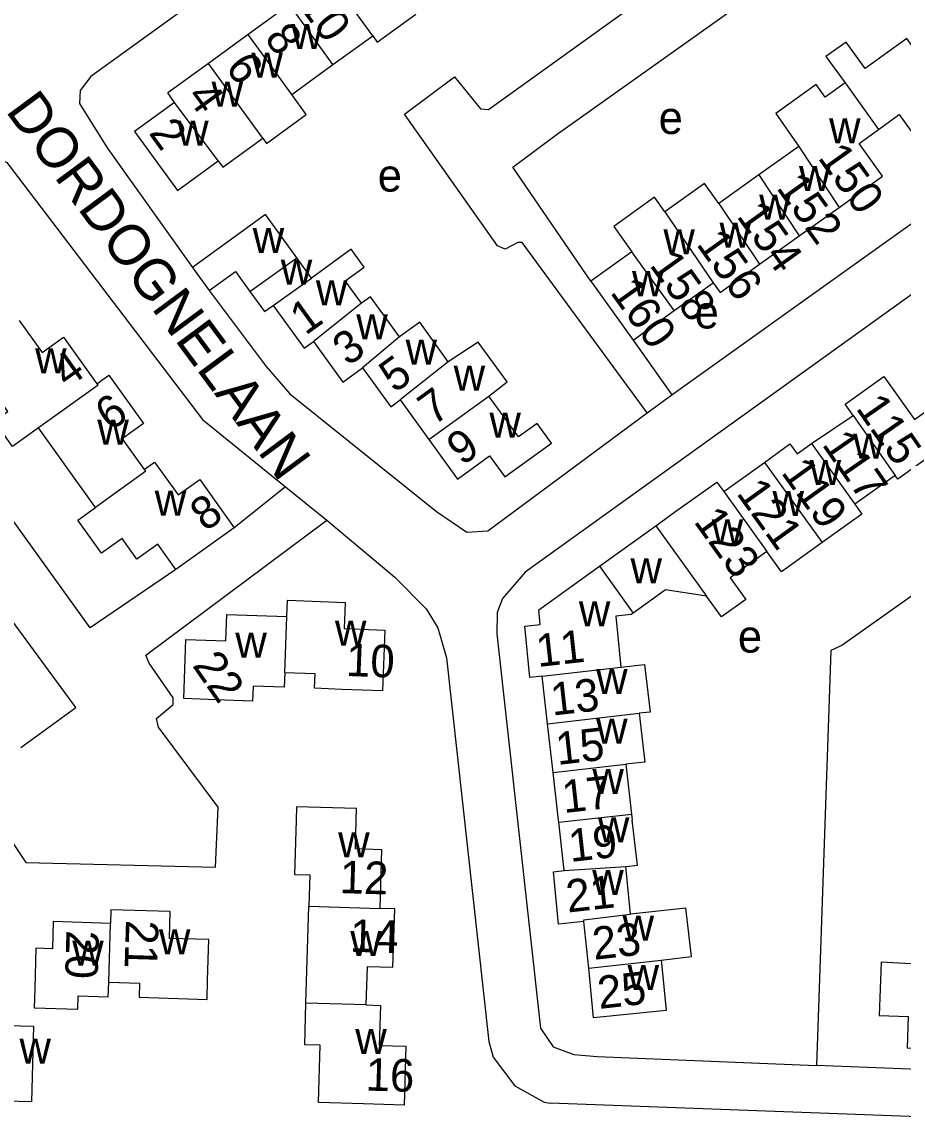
# Model space of a CAD drawing. Extents: x 157768 to 159790, y 387230 to 389604.
# Drawn here: x 159313.5 to 159421.7, y 387713.3 to 387848 of the extents above; entities that cross this region are included whole.
import ezdxf

# ---------------------------------------------------------------- set-up
doc = ezdxf.new("R2010")
doc.units = 0
for name, color, linetype in [('BLT_Basislijn', 7, 'Continuous'), ('BLT_Bebouwing', 7, 'Continuous'), ('BLT_Centroide', 7, 'Continuous'), ('BLT_Huisnummer', 7, 'Continuous'), ('BLT_Huisnummer_ tussenligend', 7, 'Continuous'), ('BLT_Onderverdeling_panden', 7, 'Continuous'), ('BLT_Straatnaam', 7, 'Continuous')]:
    doc.layers.add(name, color=color, linetype=linetype)

msp = doc.modelspace()

# ---------------------------------------------------------------- linework, layer by layer
at = {"layer": 'BLT_Basislijn'}
for p, q in [((159388.55, 387808.92), (159393.32, 387802.2)), ((159390.28, 387799.97), (159393.32, 387802.2)), ((159345.89, 387790.89), (159339.59, 387785.87)), ((159345.89, 387790.89), (159350.94, 387786.79))]:
    msp.add_line(p, q, dxfattribs=at)
for points in [[(159369.02, 387875.27), (159321.99, 387841.27), (159320.67, 387839.54), (159320.57, 387837.93), (159324, 387832.5), (159334.45, 387817.83)], [(159390.28, 387799.97), (159374.93, 387820.87), (159374.4, 387820.9), (159372.85, 387820.06), (159371.89, 387820.49), (159360.49, 387836.65), (159366.62, 387841.23), (159369.82, 387837.31), (159370.78, 387837.23), (159412.51, 387867.2)], [(159383.37, 387816.16), (159373.78, 387830.14), (159379.12, 387834.12), (159416.97, 387861.01)], [(159393.32, 387802.2), (159394.32, 387802.93), (159437.92, 387834.07), (159438.12, 387834.28)], [(159219.5, 387769.45), (159262.12, 387800.73), (159305.97, 387831.61), (159309.16, 387831.8), (159311.67, 387830.69), (159335.68, 387799.17), (159345.89, 387790.89)], [(159445.3, 387826.26), (159440.05, 387825.99), (159434.86, 387823.21), (159375.3, 387780.41), (159372.53, 387777.2), (159371.86, 387775.48), (159371.82, 387772.86), (159377.17, 387724.46), (159378.74, 387722.16), (159381.29, 387721.21), (159384.15, 387720.97), (159411.05, 387719.86)], [(159336.49, 387814.98), (159343.52, 387805.65), (159346.42, 387802.32), (159364.42, 387787.88), (159368.15, 387785.35), (159370.7, 387785.49), (159390.28, 387799.97)], [(159332.42, 387780.74), (159321.9, 387773.6), (159309.5, 387790.76), (159307.4, 387793.43), (159306.23, 387794.04), (159272.12, 387769.71), (159266.7, 387765.6), (159264.67, 387762.77), (159241.21, 387746.13), (159238.71, 387746.33), (159236.06, 387744.01), (159232.04, 387749.26)], [(159307.37, 387754.7), (159314, 387744.78), (159337.28, 387744.2), (159337.6, 387751.56), (159330.28, 387761.42), (159330.06, 387762.45), (159332.09, 387764.2), (159332.09, 387765), (159329.13, 387769.25), (159328.74, 387770.25), (159350.94, 387786.79)], [(159350.94, 387786.79), (159359.3, 387779.83), (159363.14, 387775.91), (159364.57, 387773.6), (159365.65, 387769.93), (159370.85, 387722.83), (159371.39, 387720.88), (159374.04, 387717.39), (159377.63, 387715.38), (159378.37, 387715.23)], [(159313.39, 387758.89), (159320.15, 387763.81), (159306.22, 387782.73), (159298.09, 387777.75)], [(159424.28, 387778.6), (159414.19, 387771.43), (159412.82, 387770.79), (159411.05, 387719.86)], [(159452.31, 387759.99), (159452.15, 387759.68), (159439.38, 387720.69), (159436.61, 387719.06), (159434, 387718.98), (159411.05, 387719.86)], [(159535.77, 387748.36), (159535.14, 387748.73), (159527.81, 387753.01), (159522.21, 387754.81), (159457.94, 387756.72), (159444.24, 387717.83), (159443.55, 387716.48), (159440.68, 387713.82), (159439.41, 387713.3), (159428, 387713.39), (159378.37, 387715.23)]]:
    msp.add_lwpolyline(points, dxfattribs=at)
at = {"layer": 'BLT_Bebouwing'}
for p, q in [((159346.35, 387850.09), (159341.3, 387846.43)), ((159341.3, 387846.43), (159336.41, 387842.88)), ((159336.41, 387842.88), (159331.42, 387839.27)), ((159346.64, 387839.07), (159351.69, 387842.73)), ((159332.27, 387838.09), (159331.42, 387839.27)), ((159408.88, 387832.68), (159404, 387829.19)), ((159404, 387829.19), (159399.08, 387825.66)), ((159408.95, 387821.7), (159413.83, 387825.2)), ((159404.07, 387818.21), (159408.95, 387821.7)), ((159388.4, 387819.76), (159383.37, 387816.16)), ((159383.37, 387816.16), (159388.55, 387808.92)), ((159393.59, 387812.53), (159398.37, 387815.95)), ((159388.55, 387808.92), (159393.59, 387812.53)), ((159359.95, 387801.56), (159363.47, 387796.71)), ((159410.43, 387796.2), (159415.58, 387799.65)), ((159407.8, 387796.16), (159408.67, 387794.94)), ((159408.67, 387794.94), (159410.43, 387796.2)), ((159399.67, 387790.31), (159404.66, 387793.9)), ((159339.59, 387785.87), (159332.42, 387780.74)), ((159384.43, 387781.15), (159391.34, 387786.12)), ((159386.42, 387775.04), (159387.05, 387768.76)), ((159378.04, 387761.81), (159377.37, 387767.66)), ((159378.72, 387755.83), (159378.04, 387761.81)), ((159387.65, 387756.85), (159388.36, 387750.74)), ((159379.39, 387750), (159378.72, 387755.83)), ((159388.36, 387750.74), (159388.44, 387750)), ((159379.43, 387749.72), (159379.39, 387750)), ((159380.1, 387743.79), (159379.43, 387749.72)), ((159388.24, 387738.45), (159387.65, 387744.31)), ((159383.1, 387731.8), (159382.52, 387737.55))]:
    msp.add_line(p, q, dxfattribs=at)
for points in [[(159356.58, 387846.27), (159357.15, 387845.47), (159361.89, 387848.91)], [(159351.69, 387842.73), (159356.58, 387846.27)], [(159424.73, 387842.32), (159422.16, 387845.91), (159417.02, 387842.23), (159414.7, 387845.47), (159412.22, 387843.71), (159414.57, 387840.48)], [(159414.57, 387840.48), (159412.13, 387838.73), (159411.02, 387840.27), (159406.05, 387836.71), (159408.88, 387832.68)], [(159332.27, 387838.09), (159327.35, 387834.52), (159332.61, 387827.26), (159337.63, 387830.9)], [(159343.08, 387833.68), (159343.54, 387833.04), (159348.43, 387836.59), (159346.64, 387839.07)], [(159418.67, 387834.76), (159421.22, 387836.58), (159424.94, 387831.39), (159429.97, 387834.99)], [(159413.83, 387825.2), (159419.18, 387829.02), (159416.29, 387833.05), (159418.67, 387834.76)], [(159337.63, 387830.9), (159338.18, 387830.13), (159343.08, 387833.68)], [(159399.08, 387825.66), (159397.31, 387828.12), (159392.44, 387824.64)], [(159392.44, 387824.64), (159391.19, 387826.45), (159386.19, 387822.87), (159388.4, 387819.76)], [(159347.25, 387819.02), (159345.46, 387821.49), (159343.41, 387824.32), (159334.45, 387817.83)], [(159355.2, 387813.44), (159353.22, 387816.17), (159355.55, 387817.86), (159353.95, 387820.06), (159349.06, 387816.52)], [(159334.45, 387817.83), (159336.49, 387814.98)], [(159349.06, 387816.52), (159347.25, 387819.02)], [(159398.37, 387815.95), (159399.23, 387814.74), (159404.07, 387818.21)], [(159336.49, 387814.98), (159339.73, 387817.33), (159341.51, 387814.86)], [(159341.51, 387814.86), (159343.3, 387812.4), (159344.36, 387813.17)], [(159359.89, 387809.3), (159356.31, 387814.24), (159355.2, 387813.44)], [(159344.36, 387813.17), (159348.17, 387807.92), (159349.3, 387808.73)], [(159313.19, 387811.32), (159316, 387807.39), (159318.63, 387809.28), (159322.72, 387803.56)], [(159365.86, 387806.25), (159362.35, 387811.09), (159359.89, 387809.3)], [(159349.3, 387808.73), (159352.91, 387803.74), (159355.34, 387805.5)], [(159370.83, 387802.04), (159373.07, 387803.78), (159369.53, 387808.66), (159365.86, 387806.25)], [(159315.56, 387798.14), (159312.35, 387795.84), (159310.12, 387798.96), (159311.8, 387800.16), (159306.99, 387806.89)], [(159322.72, 387803.56), (159324.19, 387804.61), (159328.44, 387798.68), (159325.82, 387796.81), (159328.53, 387793.02)], [(159355.34, 387805.5), (159358.8, 387800.72), (159359.95, 387801.56)], [(159415.58, 387799.65), (159414.59, 387801.03), (159419.32, 387804.43), (159423.1, 387799.18), (159425.66, 387801.02)], [(159363.47, 387796.71), (159366.98, 387791.86), (159370.93, 387794.71), (159372.8, 387792.12), (159378.52, 387796.27), (159376.76, 387798.69), (159374.46, 387797.03), (159370.83, 387802.04)], [(159322.55, 387788.36), (159315.56, 387798.14)], [(159404.66, 387793.9), (159407.8, 387796.16)], [(159429.84, 387795.21), (159427.36, 387793.43), (159425.97, 387795.36), (159421.06, 387791.83), (159420.71, 387792.31)], [(159328.53, 387793.02), (159329.8, 387793.93), (159332.69, 387789.9), (159335.35, 387791.8), (159339.59, 387785.87)], [(159420.71, 387792.31), (159415.77, 387788.76)], [(159391.34, 387786.12), (159393.81, 387787.9), (159398.81, 387791.49)], [(159398.81, 387791.49), (159399.67, 387790.31)], [(159332.42, 387780.74), (159330.19, 387783.86), (159327.63, 387782.03), (159325.83, 387784.56), (159323.3, 387782.75), (159320.39, 387786.82), (159322.55, 387788.36)], [(159415.77, 387788.76), (159416.63, 387787.56), (159411.76, 387784.06)], [(159404.96, 387782.97), (159400.46, 387779.74), (159402.38, 387777.08)], [(159411.76, 387784.06), (159406.76, 387780.46), (159404.96, 387782.97)], [(159377.16, 387774), (159376.98, 387775.79), (159384.43, 387781.15)], [(159397.56, 387777.49), (159392.54, 387778.27), (159388.56, 387775.41)], [(159402.38, 387777.08), (159399.4, 387774.93), (159397.56, 387777.49)], [(159346.05, 387774.97), (159346.13, 387776.98), (159353.2, 387776.71), (159353.08, 387773.51), (159358.06, 387773.32), (159357.78, 387765.86), (159352.78, 387766.04), (159349.43, 387766.17), (159349.5, 387767.93), (159345.79, 387768.07)], [(159345.79, 387768.07), (159345.72, 387766.29), (159341.9, 387766.43), (159341.83, 387764.59), (159338.38, 387764.72), (159333.39, 387764.9), (159333.66, 387772.17), (159338.56, 387771.98), (159338.68, 387775.24), (159346.05, 387774.97)], [(159388.56, 387775.41), (159388.31, 387775.23), (159386.42, 387775.04)], [(159377.37, 387767.66), (159375.87, 387767.48), (159375.24, 387773.8), (159377.16, 387774)], [(159387.05, 387768.76), (159389.96, 387769.1), (159390.64, 387763.26), (159389.28, 387763.1)], [(159389.28, 387763.1), (159389.97, 387757.12), (159387.65, 387756.85)], [(159354.56, 387750), (159354.6, 387751.42), (159347.24, 387751.64), (159347.19, 387750)], [(159347.19, 387750), (159346.98, 387743.31), (159348.86, 387743.26), (159348.75, 387739.42)], [(159357.49, 387739.16), (159357.71, 387746.35), (159354.45, 387746.45), (159354.56, 387750)], [(159387.65, 387744.31), (159389.08, 387744.46), (159388.44, 387750)], [(159382.52, 387737.55), (159379.4, 387737.23), (159378.76, 387743.64), (159380.1, 387743.79)], [(159324.17, 387730.1), (159327.95, 387729.99), (159327.9, 387728.24), (159336.25, 387727.99), (159336.32, 387730.33), (159336.47, 387735.33), (159331.62, 387735.47), (159331.72, 387738.76), (159324.44, 387738.98), (159324.39, 387737.32)], [(159348.38, 387727.52), (159348.75, 387739.42)], [(159355.8, 387727.3), (159355.94, 387732.02), (159359.06, 387731.93), (159359.28, 387739.1), (159357.49, 387739.16)], [(159392, 387732.82), (159395.7, 387733.25), (159395.02, 387739.17), (159388.24, 387738.45)], [(159324.39, 387737.32), (159317.37, 387737.53), (159317.27, 387734.21), (159315.24, 387734.27), (159315.1, 387729.27), (159315.03, 387726.96), (159320.39, 387726.8), (159320.44, 387728.43), (159324.12, 387728.32), (159324.17, 387730.1)], [(159392, 387732.82), (159392.12, 387731.6), (159392.62, 387726.62), (159383.7, 387725.73), (159383.1, 387731.8)], [(159426.24, 387732.15), (159418.99, 387732.56), (159418.77, 387726.02), (159422.3, 387725.89), (159422.18, 387722.06), (159431.41, 387721.76), (159431.54, 387725.56), (159432.83, 387725.51), (159433.04, 387731.93)], [(159355.8, 387727.3), (159357.52, 387727.24), (159357.37, 387722.34), (159360.66, 387722.24), (159360.44, 387714.99), (159355.44, 387715.15), (159349.93, 387715.31), (159350.14, 387722.36), (159348.23, 387722.42), (159348.38, 387727.52)], [(159311.73, 387724.79), (159314.96, 387724.69), (159314.68, 387715.42), (159311.47, 387715.51)]]:
    msp.add_lwpolyline(points, dxfattribs=at)
at = {"layer": 'BLT_Onderverdeling_panden'}
for p, q in [((159351.69, 387842.73), (159346.35, 387850.09)), ((159346.64, 387839.07), (159341.3, 387846.43)), ((159343.08, 387833.68), (159336.41, 387842.88)), ((159414.57, 387840.48), (159418.67, 387834.76)), ((159337.63, 387830.9), (159332.27, 387838.09)), ((159408.88, 387832.68), (159413.83, 387825.2)), ((159404, 387829.19), (159408.95, 387821.7)), ((159392.44, 387824.64), (159398.37, 387815.95)), ((159399.08, 387825.66), (159404.07, 387818.21)), ((159393.59, 387812.53), (159388.4, 387819.76)), ((159341.51, 387814.86), (159347.25, 387819.02)), ((159344.36, 387813.17), (159349.06, 387816.52)), ((159355.2, 387813.44), (159349.3, 387808.73)), ((159359.89, 387809.3), (159355.34, 387805.5)), ((159365.86, 387806.25), (159359.95, 387801.56)), ((159363.47, 387796.71), (159370.83, 387802.04)), ((159415.58, 387799.65), (159420.71, 387792.31)), ((159410.43, 387796.2), (159415.77, 387788.76)), ((159399.67, 387790.31), (159404.96, 387782.97)), ((159391.34, 387786.12), (159397.56, 387777.49)), ((159384.43, 387781.15), (159388.56, 387775.41)), ((159345.79, 387768.07), (159346.05, 387774.97)), ((159377.37, 387767.66), (159387.05, 387768.76)), ((159378.04, 387761.81), (159389.28, 387763.1)), ((159378.72, 387755.83), (159387.65, 387756.85)), ((159379.43, 387749.72), (159388.36, 387750.74)), ((159380.1, 387743.79), (159387.65, 387744.31)), ((159348.75, 387739.42), (159357.49, 387739.16)), ((159324.17, 387730.1), (159324.39, 387737.32)), ((159383.1, 387731.8), (159392, 387732.82)), ((159355.8, 387727.3), (159348.38, 387727.52))]:
    msp.add_line(p, q, dxfattribs=at)
for points in [[(159356.58, 387846.27), (159351.24, 387853.64), (159350.95, 387853.42)], [(159322.72, 387803.56), (159322.86, 387803.36), (159315.56, 387798.14)], [(159404.66, 387793.9), (159405.54, 387792.69)], [(159328.53, 387793.02), (159328.75, 387792.82), (159322.55, 387788.36)], [(159405.54, 387792.69), (159411.76, 387784.06)], [(159382.52, 387737.55), (159382.49, 387737.75), (159388.24, 387738.45)]]:
    msp.add_lwpolyline(points, dxfattribs=at)

# ---------------------------------------------------------------- texts
at = {"layer": 'BLT_Centroide'}
for s, p in [('w', (159346.58, 387844.64)), ('w', (159341.69, 387841.11)), ('w', (159336.81, 387837.55)), ('e', (159391.68, 387834.21)), ('w', (159332.58, 387832.78)), ('w', (159412.61, 387833.05)), ('e', (159357.2, 387827.14)), ('w', (159408.92, 387827.19)), ('w', (159404.03, 387823.69)), ('w', (159399.16, 387820.25)), ('w', (159341.85, 387819.59)), ('w', (159392.27, 387819.45)), ('w', (159345.3, 387815.72)), ('w', (159388.42, 387814.3)), ('w', (159349.61, 387813.16)), ('e', (159396.1, 387810.34)), ('w', (159354.57, 387809)), ('w', (159360.62, 387805.91)), ('w', (159315.14, 387804.84)), ('w', (159366.52, 387802.69)), ('w', (159322.78, 387796.06)), ('w', (159370.91, 387796.94)), ('w', (159415.56, 387794.34)), ('w', (159410.22, 387791.11)), ('w', (159329.83, 387787.34)), ('w', (159405.66, 387787.31)), ('w', (159398.2, 387783.83)), ('w', (159388.23, 387779.05)), ('w', (159381.89, 387773.77)), ('w', (159351.95, 387771.41)), ('e', (159401.41, 387770.55)), ('w', (159339.72, 387769.91)), ('w', (159384.01, 387765.47)), ('w', (159384.01, 387759.38)), ('w', (159383.55, 387753.19)), ('w', (159384.23, 387747.28)), ('w', (159352.34, 387745.41)), ('w', (159383.53, 387740.78)), ('w', (159387.26, 387735.19)), ('w', (159330.34, 387733.5)), ('w', (159353.83, 387733.31)), ('w', (159319.7, 387732.14)), ('w', (159387.87, 387729.12)), ('w', (159354.44, 387721.27)), ('w', (159313.22, 387720.11))]:
    msp.add_text(s, height=4, dxfattribs=at).set_placement(p)
at = {"layer": 'BLT_Huisnummer'}
for s, rotation, p in [('10', 305.9409, (159347.42, 387849.98)), ('6', 305.9409, (159338.4, 387842.37)), ('2', 305.9409, (159329.01, 387834.32)), ('150', 305.6065, (159411.14, 387831.29)), ('154', 305.6065, (159401.17, 387824.11)), ('160', 305.6065, (159385.65, 387814.77)), ('1', 35.933, (159348.33, 387809.41)), ('5', 35.9292, (159359.27, 387802.33)), ('115', 304.783, (159415.81, 387800.55)), ('9', 35.9262, (159367.56, 387793.4)), ('119', 305.7516, (159406.63, 387792.65)), ('8', 35.5845, (159336.04, 387785.32)), ('123', 305.7219, (159395.9, 387786.64)), ('11', 6.3402, (159376.86, 387768.78)), ('22', 304.8261, (159334.36, 387768.97)), ('10', 357.845, (159353.26, 387767.69)), ('15', 6.3402, (159379.27, 387756.76)), ('19', 6.3402, (159380.85, 387744.85)), ('12', 358.2499, (159352.49, 387741.04)), ('21', 268.2921, (159326.3, 387737.76)), ('20', 268.2921, (159318.99, 387736.51)), ('25', 6.3402, (159384.4, 387726.81)), ('16', 358.2539, (159355.68, 387716.8))]:
    msp.add_text(s, height=4, rotation=rotation, dxfattribs=at).set_placement(p)
at = {"layer": 'BLT_Huisnummer_ tussenligend'}
for s, rotation, p in [('8', 305.9409, (159343.19, 387845.96)), ('4', 305.9409, (159333.63, 387838.79)), ('152', 305.6065, (159406.04, 387827.61)), ('156', 305.6065, (159396.22, 387820.68)), ('158', 305.6065, (159390.48, 387818.11)), ('3', 35.933, (159353.55, 387805.63)), ('4', 35.5768, (159319.1, 387802.93)), ('7', 35.9292, (159364.04, 387798.33)), ('6', 35.5768, (159324.39, 387797.64)), ('117', 304.783, (159411.65, 387796.1)), ('121', 305.7516, (159401.14, 387790.11)), ('13', 6.3402, (159378.64, 387762.82)), ('17', 6.3402, (159380.05, 387750.85)), ('21', 6.3402, (159380.53, 387738.64)), ('14', 358.2499, (159353.75, 387733.84)), ('23', 6.3402, (159383.76, 387732.84))]:
    msp.add_text(s, height=4, rotation=rotation, dxfattribs=at).set_placement(p)
at = {"layer": 'BLT_Straatnaam'}
msp.add_text('DORDOGNELAAN', height=5, rotation=306.4971, dxfattribs=at).set_placement((159311.43, 387837.03))

doc.saveas('drawing.dxf')
